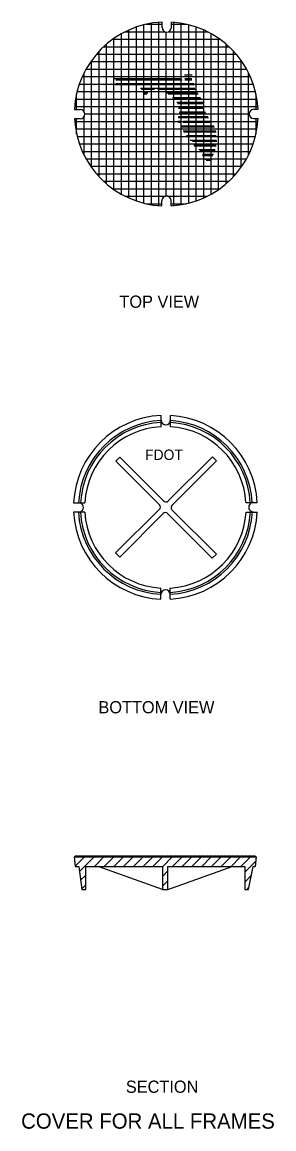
# Model space of a CAD drawing. Extents: x 4851 to 4902, y 9954.5 to 9971.9.
# Drawn here: x 4899.22 to 4901.96, y 9959.89 to 9971.92 of the extents above; entities that cross this region are included whole.
import ezdxf

# ---------------------------------------------------------------- set-up
doc = ezdxf.new("R2010")
doc.units = 0
for name, color, linetype in [('Default', 7, 'Continuous'), ('Dimension', 7, 'Continuous'), ('DSText', 7, 'Continuous'), ('SupstrConc', 7, 'Continuous'), ('TextMisc', 7, 'Continuous')]:
    doc.layers.add(name, color=color, linetype=linetype)

msp = doc.modelspace()

# ---------------------------------------------------------------- linework, layer by layer
at = {"layer": 'Default'}
for p, q in [((4900.986, 9971.347), (4901.07, 9971.347)), ((4900.224, 9971.307), (4900.953, 9971.307)), ((4900.233, 9971.244), (4901.092, 9971.244)), ((4900.242, 9971.295), (4900.963, 9971.295)), ((4900.242, 9971.255), (4901.089, 9971.255)), ((4900.992, 9971.307), (4901.069, 9971.307)), ((4900.993, 9971.295), (4901.066, 9971.295)), ((4900.511, 9971.204), (4901.1, 9971.204)), ((4900.521, 9971.193), (4900.661, 9971.193)), ((4900.542, 9971.152), (4900.588, 9971.152)), ((4900.546, 9971.141), (4900.579, 9971.141)), ((4900.696, 9971.193), (4901.103, 9971.193)), ((4900.797, 9971.152), (4901.128, 9971.152)), ((4900.81, 9971.141), (4901.137, 9971.141)), ((4900.859, 9971.101), (4901.163, 9971.101)), ((4900.864, 9971.09), (4901.17, 9971.09)), ((4900.904, 9971.05), (4901.19, 9971.05)), ((4900.911, 9971.038), (4901.191, 9971.038)), ((4900.923, 9970.998), (4901.19, 9970.998)), ((4900.923, 9970.987), (4901.191, 9970.987)), ((4900.919, 9970.884), (4901.249, 9970.884)), ((4900.921, 9970.896), (4901.242, 9970.896)), ((4900.931, 9970.936), (4901.22, 9970.936)), ((4900.932, 9970.947), (4901.213, 9970.947)), ((4900.914, 9970.844), (4900.944, 9970.844)), ((4900.924, 9970.833), (4900.939, 9970.833)), ((4900.953, 9970.782), (4901.314, 9970.782)), ((4900.957, 9970.793), (4901.306, 9970.793)), ((4900.973, 9970.833), (4901.28, 9970.833)), ((4900.974, 9970.741), (4901.33, 9970.741)), ((4900.976, 9970.844), (4901.273, 9970.844)), ((4900.982, 9970.73), (4901.332, 9970.73)), ((4901.009, 9970.69), (4901.332, 9970.69)), ((4901.014, 9970.679), (4901.332, 9970.679)), ((4901.049, 9970.639), (4901.337, 9970.639)), ((4901.075, 9970.628), (4901.339, 9970.628)), ((4901.09, 9970.587), (4901.332, 9970.587)), ((4901.094, 9970.576), (4901.332, 9970.576)), ((4901.143, 9970.536), (4901.322, 9970.536)), ((4901.157, 9970.525), (4901.322, 9970.525)), ((4901.184, 9970.485), (4901.303, 9970.485)), ((4901.184, 9970.473), (4901.296, 9970.473)), ((4901.21, 9970.433), (4901.284, 9970.433)), ((4901.224, 9970.422), (4901.275, 9970.422))]:
    msp.add_line(p, q, dxfattribs=at)
at = {"layer": 'Dimension'}
for p, q in [((4900.342, 9971.817), (4900.776, 9971.817)), ((4900.384, 9970.009), (4900.384, 9971.836)), ((4900.465, 9969.977), (4900.465, 9971.868)), ((4900.546, 9969.953), (4900.546, 9971.892)), ((4900.57, 9971.898), (4900.744, 9971.898)), ((4900.628, 9969.936), (4900.628, 9971.909)), ((4900.709, 9969.926), (4900.709, 9971.919)), ((4900.744, 9971.863), (4900.744, 9971.922)), ((4900.813, 9971.817), (4901.238, 9971.817)), ((4900.845, 9971.863), (4900.845, 9971.921)), ((4900.845, 9971.898), (4901.011, 9971.898)), ((4900.872, 9969.926), (4900.872, 9971.919)), ((4900.953, 9969.936), (4900.953, 9971.909)), ((4901.034, 9969.953), (4901.034, 9971.892)), ((4901.115, 9969.977), (4901.115, 9971.868)), ((4901.197, 9970.009), (4901.197, 9971.836)), ((4900.208, 9971.735), (4901.373, 9971.735)), ((4900.221, 9970.1), (4900.221, 9971.745)), ((4900.303, 9970.05), (4900.303, 9971.796)), ((4900.79, 9970.03), (4900.79, 9971.813)), ((4901.278, 9970.05), (4901.278, 9971.796)), ((4901.359, 9970.1), (4901.359, 9971.745)), ((4900.059, 9970.241), (4900.059, 9971.604)), ((4900.108, 9971.654), (4901.472, 9971.654)), ((4900.14, 9970.163), (4900.14, 9971.682)), ((4901.44, 9970.163), (4901.44, 9971.682)), ((4901.522, 9970.241), (4901.522, 9971.604)), ((4899.968, 9971.492), (4901.613, 9971.492)), ((4899.977, 9970.34), (4899.977, 9971.505)), ((4900.031, 9971.573), (4901.55, 9971.573)), ((4901.603, 9970.34), (4901.603, 9971.505)), ((4899.896, 9970.946), (4899.896, 9971.371)), ((4899.917, 9971.41), (4901.663, 9971.41)), ((4901.684, 9970.475), (4901.684, 9971.371)), ((4899.845, 9971.248), (4901.736, 9971.248)), ((4899.877, 9971.329), (4901.704, 9971.329)), ((4899.815, 9970.97), (4899.815, 9971.143)), ((4899.82, 9971.167), (4901.76, 9971.167)), ((4901.766, 9970.974), (4901.766, 9971.143)), ((4899.794, 9971.004), (4901.787, 9971.004)), ((4899.804, 9971.085), (4901.777, 9971.085)), ((4901.74, 9970.974), (4901.789, 9970.974)), ((4899.791, 9970.97), (4899.853, 9970.97)), ((4899.854, 9970.87), (4899.792, 9970.87)), ((4899.815, 9970.702), (4899.815, 9970.87)), ((4899.896, 9970.475), (4899.896, 9970.894)), ((4899.903, 9970.923), (4901.69, 9970.923)), ((4901.741, 9970.872), (4901.789, 9970.872)), ((4901.766, 9970.702), (4901.766, 9970.872)), ((4899.794, 9970.841), (4901.787, 9970.841)), ((4899.804, 9970.76), (4901.777, 9970.76)), ((4899.82, 9970.679), (4901.76, 9970.679)), ((4899.845, 9970.598), (4901.736, 9970.598)), ((4899.877, 9970.516), (4901.704, 9970.516)), ((4899.917, 9970.435), (4901.663, 9970.435)), ((4899.968, 9970.354), (4901.613, 9970.354)), ((4900.031, 9970.272), (4901.55, 9970.272)), ((4900.108, 9970.191), (4901.472, 9970.191)), ((4900.208, 9970.11), (4901.373, 9970.11)), ((4900.342, 9970.029), (4900.782, 9970.029)), ((4900.802, 9970.029), (4901.238, 9970.029)), ((4900.57, 9969.947), (4900.742, 9969.947)), ((4900.742, 9969.924), (4900.742, 9969.978)), ((4900.843, 9969.924), (4900.843, 9969.976)), ((4900.843, 9969.947), (4901.011, 9969.947)), ((4900.733, 9967.523), (4900.733, 9967.646)), ((4900.836, 9967.522), (4900.836, 9967.646)), ((4900.242, 9967.147), (4900.286, 9967.191)), ((4900.716, 9966.674), (4900.242, 9967.147)), ((4900.76, 9966.718), (4900.286, 9967.191)), ((4900.81, 9966.715), (4901.292, 9967.196)), ((4900.855, 9966.671), (4901.336, 9967.152)), ((4901.336, 9967.152), (4901.292, 9967.196)), ((4899.781, 9966.694), (4899.904, 9966.694)), ((4901.657, 9966.698), (4901.779, 9966.698)), ((4899.903, 9966.593), (4899.782, 9966.593)), ((4900.239, 9966.15), (4900.712, 9966.623)), ((4900.283, 9966.105), (4900.757, 9966.579)), ((4901.29, 9966.093), (4900.807, 9966.576)), ((4901.334, 9966.137), (4900.851, 9966.62)), ((4901.658, 9966.595), (4901.779, 9966.595)), ((4900.283, 9966.105), (4900.239, 9966.15)), ((4901.29, 9966.093), (4901.334, 9966.137)), ((4900.732, 9965.647), (4900.732, 9965.769)), ((4900.833, 9965.648), (4900.833, 9965.769)), ((4899.789, 9962.845), (4901.768, 9962.845)), ((4899.789, 9962.845), (4899.799, 9962.741)), ((4901.768, 9962.845), (4901.757, 9962.741)), ((4899.799, 9962.741), (4899.838, 9962.741)), ((4899.838, 9962.741), (4899.872, 9962.491)), ((4899.914, 9962.491), (4899.914, 9962.741)), ((4899.914, 9962.741), (4900.748, 9962.741)), ((4900.748, 9962.741), (4900.748, 9962.491)), ((4900.808, 9962.491), (4900.808, 9962.741)), ((4900.808, 9962.741), (4901.643, 9962.741)), ((4901.643, 9962.741), (4901.643, 9962.491)), ((4901.685, 9962.491), (4901.733, 9962.741)), ((4901.733, 9962.741), (4901.757, 9962.741)), ((4899.872, 9962.491), (4899.914, 9962.491)), ((4900.748, 9962.491), (4900.808, 9962.491)), ((4901.643, 9962.491), (4901.685, 9962.491))]:
    msp.add_line(p, q, dxfattribs=at)
for centre, radius, start, end in [((4900.79, 9970.923), 1, 92.672, 177.2727), ((4900.794, 9971.864), 0.0508, 181.118, 358.882), ((4900.79, 9970.923), 1, 2.9489, 86.8545), ((4901.74, 9970.923), 0.0508, 90.3667, 270.3667), ((4900.79, 9970.923), 1, 183.0429, 267.2304), ((4899.853, 9970.92), 0.0503, 271.5242, 90), ((4900.79, 9970.923), 1, 273.0077, 357.1063), ((4900.792, 9969.979), 0.0505, 356.3881, 181.8108), ((4900.78, 9966.646), 1, 92.7004, 177.2547), ((4900.78, 9966.646), 1, 2.9489, 86.8361), ((4900.78, 9966.646), 0.945, 92.8459, 177.0472), ((4900.78, 9966.646), 0.924, 92.9126, 176.9967), ((4900.78, 9966.646), 0.878, 93.0642, 176.8779), ((4900.785, 9967.594), 0.0511, 181.8358, 0.5083), ((4900.78, 9966.646), 0.878, 3.3597, 86.409), ((4900.78, 9966.646), 0.945, 3.1191, 86.6509), ((4900.78, 9966.646), 0.924, 3.193, 86.5716), ((4899.837, 9966.644), 0.0507, 269.459, 90), ((4900.692, 9966.65), 0.0335, 307.1159, 45.5352), ((4900.787, 9966.738), 0.0335, 217.1775, 315.472), ((4900.875, 9966.644), 0.0335, 127.2072, 225.5614), ((4901.737, 9966.647), 0.0511, 88.0533, 270.1411), ((4900.78, 9966.646), 1, 183.0753, 267.2121), ((4900.78, 9966.646), 0.947, 183.2027, 267.0558), ((4900.78, 9966.646), 0.926, 183.3296, 266.9894), ((4900.78, 9966.646), 0.879, 183.4412, 266.8276), ((4900.78, 9966.555), 0.0335, 37.1461, 135.567), ((4900.78, 9966.646), 1, 273.0277, 357.0872), ((4900.78, 9966.646), 0.947, 273.1974, 356.9239), ((4900.78, 9966.646), 0.926, 273.2696, 356.8545), ((4900.78, 9966.646), 0.879, 273.4455, 356.6852), ((4900.782, 9965.697), 0.0508, 0.8377, 180.071)]:
    msp.add_arc(centre, radius, start, end, dxfattribs=at)
at = {"layer": 'SupstrConc'}
for p, q in [((4899.795, 9962.845), (4899.799, 9962.855)), ((4899.799, 9962.855), (4899.831, 9962.855)), ((4899.831, 9962.855), (4899.837, 9962.845)), ((4899.837, 9962.845), (4899.842, 9962.855)), ((4899.842, 9962.855), (4899.874, 9962.855)), ((4899.874, 9962.855), (4899.88, 9962.845)), ((4899.88, 9962.845), (4899.885, 9962.855)), ((4899.885, 9962.855), (4899.917, 9962.855)), ((4899.917, 9962.855), (4899.923, 9962.845)), ((4899.923, 9962.845), (4899.928, 9962.855)), ((4899.928, 9962.855), (4899.959, 9962.855)), ((4899.959, 9962.855), (4899.966, 9962.845)), ((4899.966, 9962.845), (4899.97, 9962.855)), ((4899.97, 9962.855), (4900.002, 9962.855)), ((4900.002, 9962.855), (4900.008, 9962.845)), ((4900.008, 9962.845), (4900.013, 9962.855)), ((4900.013, 9962.855), (4900.045, 9962.855)), ((4900.045, 9962.855), (4900.051, 9962.845)), ((4900.051, 9962.845), (4900.056, 9962.855)), ((4900.056, 9962.855), (4900.088, 9962.855)), ((4900.088, 9962.855), (4900.094, 9962.845)), ((4900.094, 9962.845), (4900.099, 9962.855)), ((4900.099, 9962.855), (4900.13, 9962.855)), ((4900.13, 9962.855), (4900.137, 9962.845)), ((4900.137, 9962.845), (4900.141, 9962.855)), ((4900.141, 9962.855), (4900.173, 9962.855)), ((4900.173, 9962.855), (4900.179, 9962.845)), ((4900.179, 9962.845), (4900.184, 9962.855)), ((4900.184, 9962.855), (4900.216, 9962.855)), ((4900.216, 9962.855), (4900.222, 9962.845)), ((4900.222, 9962.845), (4900.227, 9962.855)), ((4900.227, 9962.855), (4900.259, 9962.855)), ((4900.259, 9962.855), (4900.265, 9962.845)), ((4900.265, 9962.845), (4900.27, 9962.855)), ((4900.27, 9962.855), (4900.302, 9962.855)), ((4900.302, 9962.855), (4900.308, 9962.845)), ((4900.308, 9962.845), (4900.313, 9962.855)), ((4900.313, 9962.855), (4900.344, 9962.855)), ((4900.344, 9962.855), (4900.35, 9962.845)), ((4900.35, 9962.845), (4900.355, 9962.855)), ((4900.355, 9962.855), (4900.387, 9962.855)), ((4900.387, 9962.855), (4900.393, 9962.845)), ((4900.393, 9962.845), (4900.398, 9962.855)), ((4900.398, 9962.855), (4900.43, 9962.855)), ((4900.43, 9962.855), (4900.436, 9962.845)), ((4900.436, 9962.845), (4900.441, 9962.855)), ((4900.441, 9962.855), (4900.473, 9962.855)), ((4900.473, 9962.855), (4900.479, 9962.845)), ((4900.479, 9962.845), (4900.484, 9962.855)), ((4900.484, 9962.855), (4900.515, 9962.855)), ((4900.515, 9962.855), (4900.522, 9962.845)), ((4900.522, 9962.845), (4900.526, 9962.855)), ((4900.526, 9962.855), (4900.558, 9962.855)), ((4900.558, 9962.855), (4900.564, 9962.845)), ((4900.564, 9962.845), (4900.569, 9962.855)), ((4900.569, 9962.855), (4900.601, 9962.855)), ((4900.601, 9962.855), (4900.607, 9962.845)), ((4900.607, 9962.845), (4900.612, 9962.855)), ((4900.612, 9962.855), (4900.644, 9962.855)), ((4900.644, 9962.855), (4900.65, 9962.845)), ((4900.65, 9962.845), (4900.655, 9962.855)), ((4900.655, 9962.855), (4900.686, 9962.855)), ((4900.686, 9962.855), (4900.693, 9962.845)), ((4900.693, 9962.845), (4900.697, 9962.856)), ((4900.697, 9962.856), (4900.729, 9962.856)), ((4900.729, 9962.856), (4900.735, 9962.845)), ((4900.735, 9962.845), (4900.74, 9962.856)), ((4900.74, 9962.856), (4900.772, 9962.856)), ((4900.772, 9962.856), (4900.778, 9962.845)), ((4900.778, 9962.845), (4900.783, 9962.856)), ((4900.783, 9962.856), (4900.815, 9962.856)), ((4900.815, 9962.856), (4900.821, 9962.845)), ((4900.821, 9962.845), (4900.826, 9962.856)), ((4900.826, 9962.856), (4900.857, 9962.856)), ((4900.857, 9962.856), (4900.864, 9962.845)), ((4900.864, 9962.845), (4900.868, 9962.856)), ((4900.868, 9962.856), (4900.9, 9962.856)), ((4900.9, 9962.856), (4900.906, 9962.845)), ((4900.906, 9962.845), (4900.911, 9962.856)), ((4900.911, 9962.856), (4900.943, 9962.856)), ((4900.943, 9962.856), (4900.949, 9962.845)), ((4900.949, 9962.845), (4900.954, 9962.856)), ((4900.954, 9962.856), (4900.986, 9962.856)), ((4900.986, 9962.856), (4900.992, 9962.845)), ((4900.992, 9962.845), (4900.997, 9962.856)), ((4900.997, 9962.856), (4901.028, 9962.856)), ((4901.028, 9962.856), (4901.035, 9962.845)), ((4901.035, 9962.845), (4901.039, 9962.856)), ((4901.039, 9962.856), (4901.071, 9962.856)), ((4901.071, 9962.856), (4901.077, 9962.845)), ((4901.077, 9962.845), (4901.082, 9962.856)), ((4901.082, 9962.856), (4901.114, 9962.856)), ((4901.114, 9962.856), (4901.12, 9962.845)), ((4901.12, 9962.845), (4901.125, 9962.856)), ((4901.125, 9962.856), (4901.157, 9962.856)), ((4901.157, 9962.856), (4901.163, 9962.845)), ((4901.163, 9962.845), (4901.168, 9962.856)), ((4901.168, 9962.856), (4901.199, 9962.856)), ((4901.199, 9962.856), (4901.206, 9962.845)), ((4901.206, 9962.845), (4901.21, 9962.856)), ((4901.21, 9962.856), (4901.242, 9962.856)), ((4901.242, 9962.856), (4901.248, 9962.845)), ((4901.248, 9962.845), (4901.253, 9962.856)), ((4901.253, 9962.856), (4901.285, 9962.856)), ((4901.285, 9962.856), (4901.291, 9962.845)), ((4901.291, 9962.845), (4901.296, 9962.856)), ((4901.296, 9962.856), (4901.328, 9962.856)), ((4901.328, 9962.856), (4901.334, 9962.845)), ((4901.334, 9962.845), (4901.339, 9962.856)), ((4901.339, 9962.856), (4901.37, 9962.856)), ((4901.37, 9962.856), (4901.377, 9962.845)), ((4901.377, 9962.845), (4901.381, 9962.856)), ((4901.381, 9962.856), (4901.413, 9962.856)), ((4901.413, 9962.856), (4901.419, 9962.845)), ((4901.419, 9962.845), (4901.424, 9962.856)), ((4901.424, 9962.856), (4901.456, 9962.856)), ((4901.456, 9962.856), (4901.462, 9962.845)), ((4901.462, 9962.845), (4901.467, 9962.856)), ((4901.467, 9962.856), (4901.499, 9962.856)), ((4901.499, 9962.856), (4901.505, 9962.845)), ((4901.505, 9962.845), (4901.51, 9962.856)), ((4901.51, 9962.856), (4901.541, 9962.856)), ((4901.541, 9962.856), (4901.548, 9962.845)), ((4901.548, 9962.845), (4901.552, 9962.856)), ((4901.552, 9962.856), (4901.584, 9962.856)), ((4901.584, 9962.856), (4901.59, 9962.845)), ((4901.59, 9962.845), (4901.595, 9962.856)), ((4901.595, 9962.856), (4901.627, 9962.856)), ((4901.627, 9962.856), (4901.633, 9962.845)), ((4901.633, 9962.845), (4901.638, 9962.856)), ((4901.638, 9962.856), (4901.67, 9962.856)), ((4901.67, 9962.856), (4901.676, 9962.845)), ((4901.676, 9962.845), (4901.681, 9962.856)), ((4901.681, 9962.856), (4901.712, 9962.856)), ((4901.712, 9962.856), (4901.719, 9962.845)), ((4901.719, 9962.845), (4901.723, 9962.856)), ((4901.723, 9962.856), (4901.755, 9962.856)), ((4901.755, 9962.856), (4901.761, 9962.845)), ((4900.748, 9962.491), (4900.049, 9962.741)), ((4900.808, 9962.491), (4901.507, 9962.741))]:
    msp.add_line(p, q, dxfattribs=at)
at = {"layer": 'TextMisc'}
for points in [[(4899.8, 9962.745), (4899.9, 9962.845)], [(4899.846, 9962.685), (4900.006, 9962.845)], [(4900.008, 9962.741), (4900.112, 9962.845)], [(4900.114, 9962.741), (4900.218, 9962.845)], [(4900.22, 9962.741), (4900.324, 9962.845)], [(4900.326, 9962.741), (4900.431, 9962.845)], [(4900.432, 9962.741), (4900.537, 9962.845)], [(4900.539, 9962.741), (4900.643, 9962.845)], [(4900.645, 9962.741), (4900.749, 9962.845)], [(4900.751, 9962.741), (4900.855, 9962.845)], [(4900.857, 9962.741), (4900.961, 9962.845)], [(4900.963, 9962.741), (4901.067, 9962.845)], [(4901.069, 9962.741), (4901.173, 9962.845)], [(4901.175, 9962.741), (4901.279, 9962.845)], [(4901.281, 9962.741), (4901.386, 9962.845)], [(4901.387, 9962.741), (4901.492, 9962.845)], [(4901.494, 9962.741), (4901.598, 9962.845)], [(4901.6, 9962.741), (4901.704, 9962.845)], [(4901.643, 9962.678), (4901.763, 9962.798)], [(4900.748, 9962.632), (4900.808, 9962.693)], [(4899.858, 9962.592), (4899.914, 9962.647)], [(4900.748, 9962.526), (4900.808, 9962.586)], [(4901.643, 9962.572), (4901.714, 9962.643)], [(4899.871, 9962.498), (4899.914, 9962.541)], [(4901.668, 9962.491), (4901.688, 9962.512)]]:
    msp.add_lwpolyline(points, dxfattribs=at)

# ---------------------------------------------------------------- texts
at = {"layer": 'DSText'}
for s, height, p in [('TOP VIEW', 0.1326, (4900.28, 9968.816)), ('FDOT', 0.1128, (4900.559, 9967.161)), ('BOTTOM VIEW', 0.13261, (4900.052, 9964.406)), ('SECTION', 0.1326, (4900.35, 9960.28)), ('COVER FOR ALL FRAMES', 0.16577, (4899.211, 9959.89))]:
    msp.add_text(s, height=height, dxfattribs=at).set_placement(p)

doc.saveas('drawing.dxf')
